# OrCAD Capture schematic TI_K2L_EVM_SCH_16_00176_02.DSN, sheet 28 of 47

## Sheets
28 PAGE15 : K2L_SOC-FPGA-AMC-1: size C; title: FPGA, SYSREF Buffering, LEDs
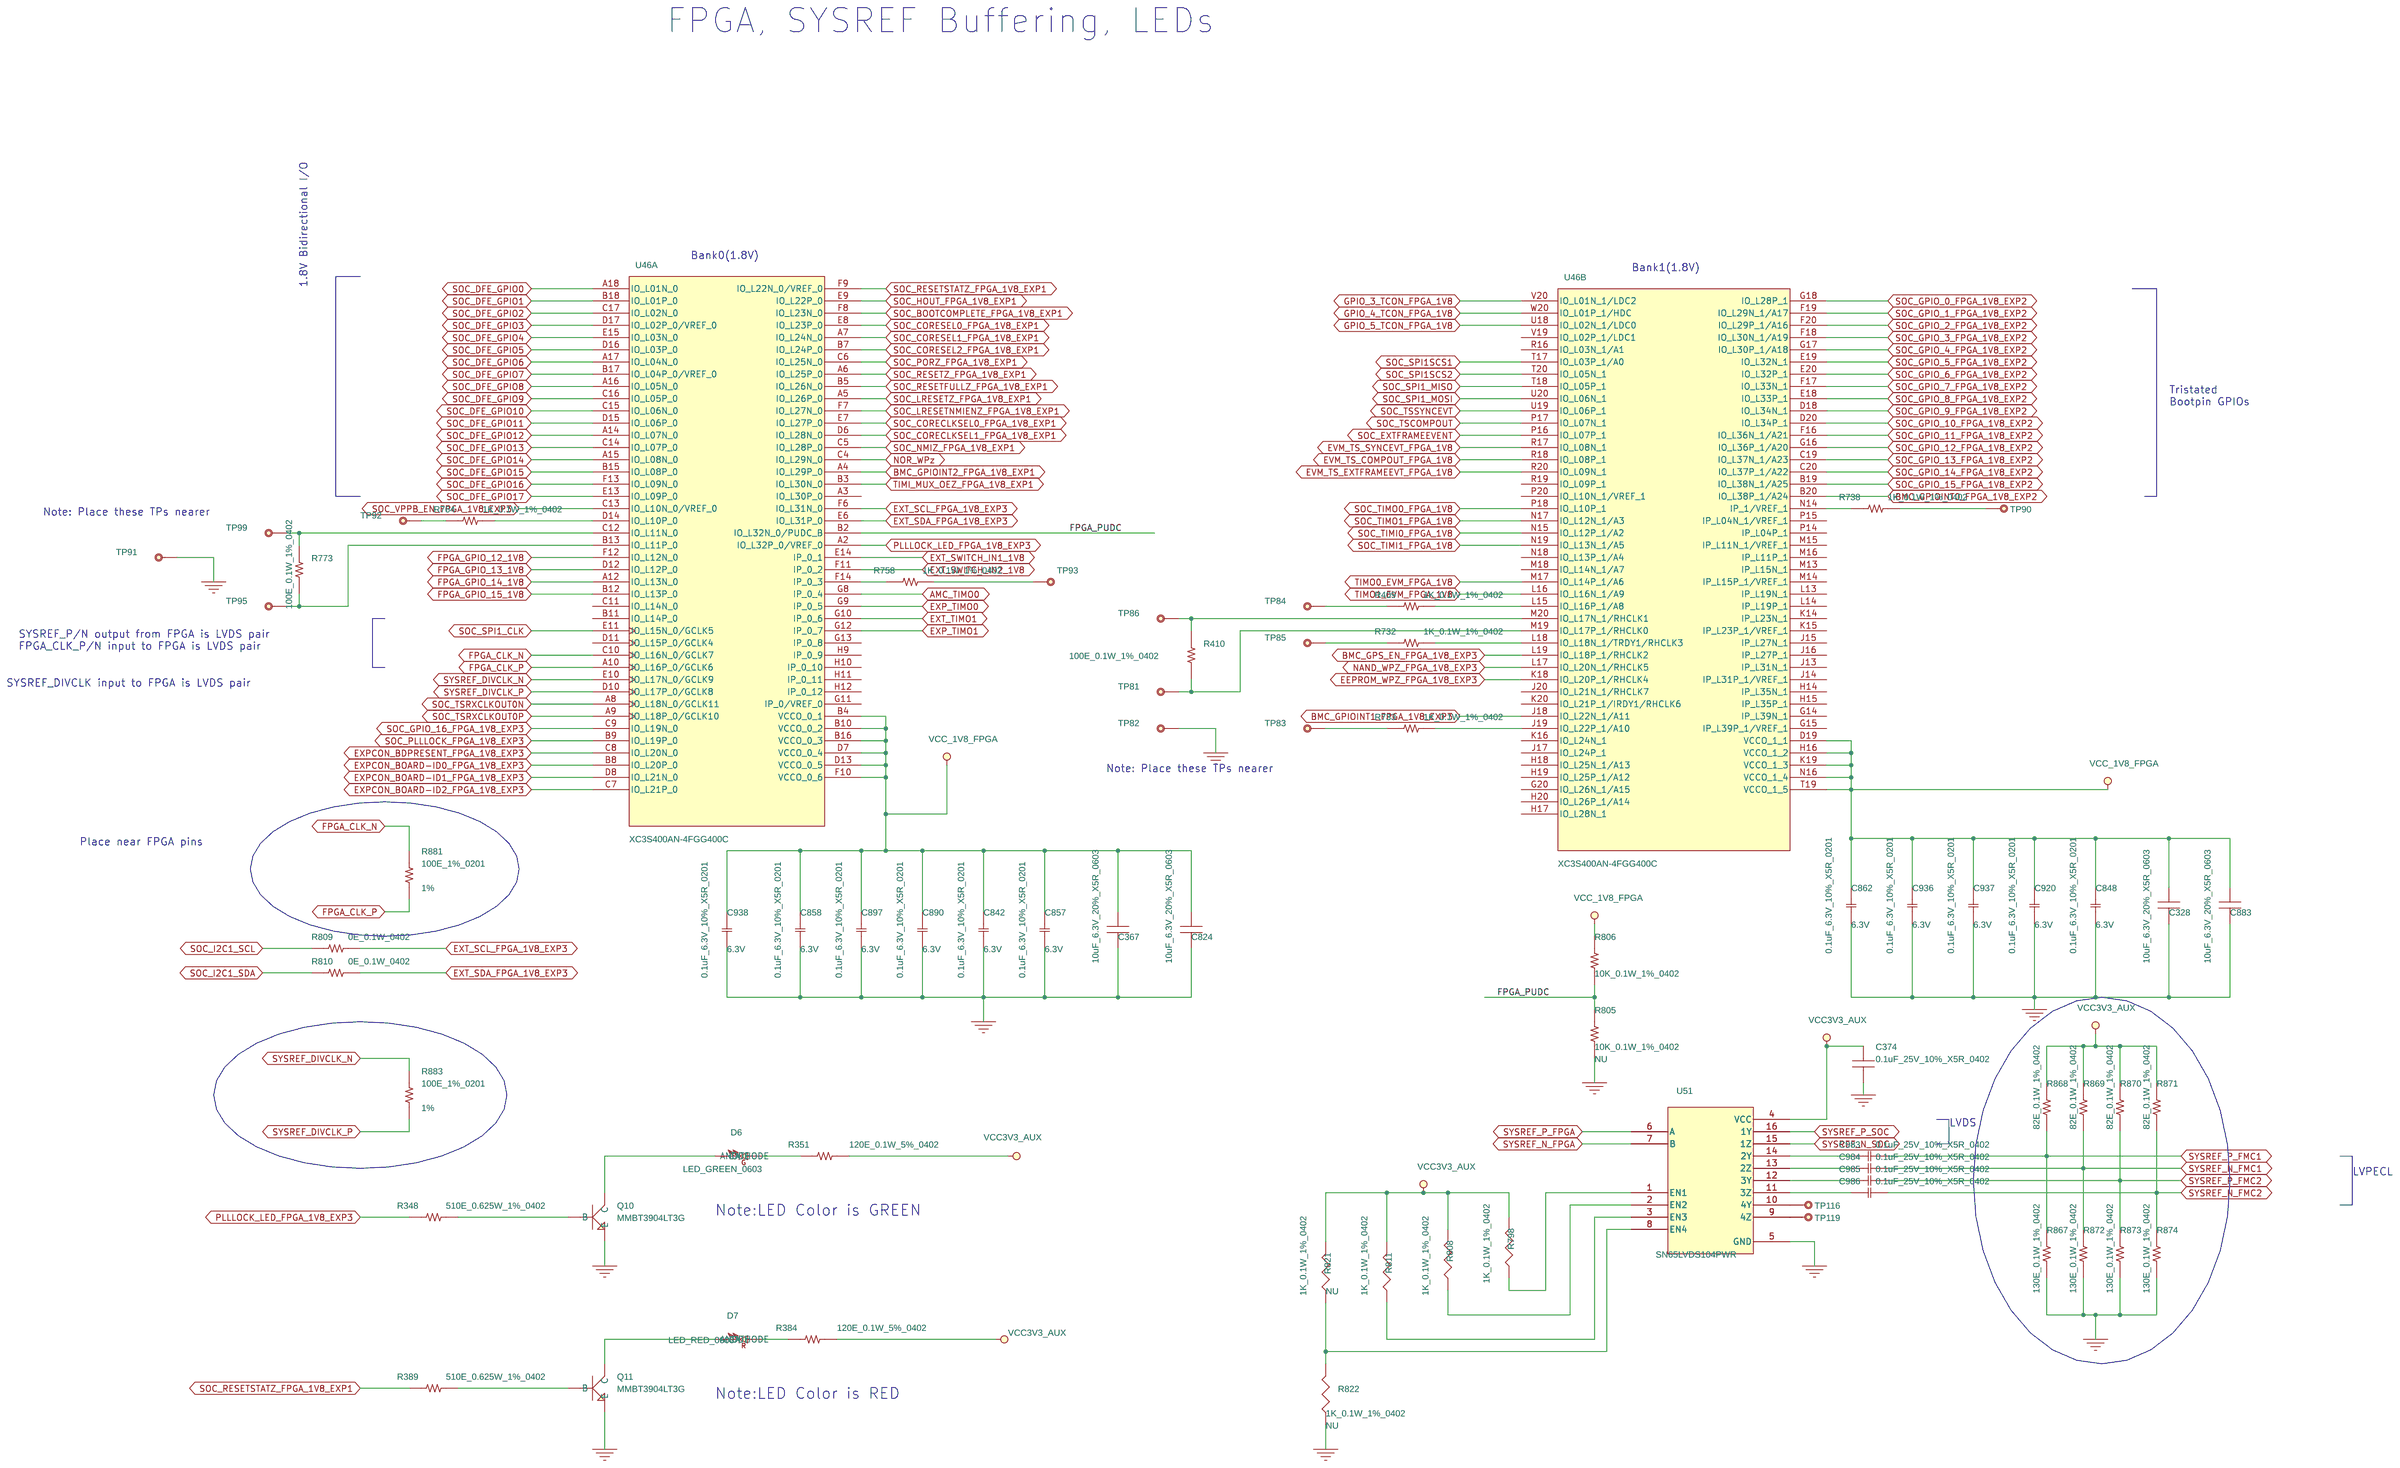
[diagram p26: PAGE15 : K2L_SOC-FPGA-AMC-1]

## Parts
sheet PAGE15 : K2L_SOC-FPGA-AMC-1
C328  10uF_6.3V_20%_X5R_0603  [C0603]
C367  10uF_6.3V_20%_X5R_0603  [C0603]
C374  0.1uF_25V_10%_X5R_0402  [C0402]
C824  10uF_6.3V_20%_X5R_0603  [C0603]
C842  0.1uF_6.3V_10%_X5R_0201  [CC0201_IPC7351_EINF]
C848  0.1uF_6.3V_10%_X5R_0201  [CC0201_IPC7351_EINF]
C857  0.1uF_6.3V_10%_X5R_0201  [CC0201_IPC7351_EINF]
C858  0.1uF_6.3V_10%_X5R_0201  [CC0201_IPC7351_EINF]
C862  0.1uF_6.3V_10%_X5R_0201  [CC0201_IPC7351_EINF]
C883  10uF_6.3V_20%_X5R_0603  [C0603]
C890  0.1uF_6.3V_10%_X5R_0201  [CC0201_IPC7351_EINF]
C897  0.1uF_6.3V_10%_X5R_0201  [CC0201_IPC7351_EINF]
C920  0.1uF_6.3V_10%_X5R_0201  [CC0201_IPC7351_EINF]
C936  0.1uF_6.3V_10%_X5R_0201  [CC0201_IPC7351_EINF]
C937  0.1uF_6.3V_10%_X5R_0201  [CC0201_IPC7351_EINF]
C938  0.1uF_6.3V_10%_X5R_0201  [CC0201_IPC7351_EINF]
C983  0.1uF_25V_10%_X5R_0402  [C0402]
C984  0.1uF_25V_10%_X5R_0402  [C0402]
C985  0.1uF_25V_10%_X5R_0402  [C0402]
C986  0.1uF_25V_10%_X5R_0402  [C0402]
D6  LED_GREEN_0603  [LED_0603]
D7  LED_RED_0603  [LED_0603]
Q10  MMBT3904LT3G  [SOT-23]
Q11  MMBT3904LT3G  [SOT-23]
R348  510E_0.625W_1%_0402  [R0402]
R351  120E_0.1W_5%_0402  [R0402]
R384  120E_0.1W_5%_0402  [R0402]
R389  510E_0.625W_1%_0402  [R0402]
R409  1K_0.1W_1%_0402  [R0402]
R410  100E_0.1W_1%_0402  [R0402]
R732  1K_0.1W_1%_0402  [R0402]
R733  1K_0.1W_1%_0402  [R0402]
R738  1K_0.1W_1%_0402  [R0402]
R758  1K_0.1W_1%_0402  [R0402]
R764  1K_0.1W_1%_0402  [R0402]
R773  100E_0.1W_1%_0402  [R0402]
R798  1K_0.1W_1%_0402  [R0402]
R805  10K_0.1W_1%_0402  [R0402]
R806  10K_0.1W_1%_0402  [R0402]
R808  1K_0.1W_1%_0402  [R0402]
R809  0E_0.1W_0402  [R0402]
R810  0E_0.1W_0402  [R0402]
R811  1K_0.1W_1%_0402  [R0402]
R821  1K_0.1W_1%_0402  [R0402]
R822  1K_0.1W_1%_0402  [R0402]
R867  130E_0.1W_1%_0402  [R0402]
R868  82E_0.1W_1%_0402  [R0402]
R869  82E_0.1W_1%_0402  [R0402]
R870  82E_0.1W_1%_0402  [R0402]
R871  82E_0.1W_1%_0402  [R0402]
R872  130E_0.1W_1%_0402  [R0402]
R873  130E_0.1W_1%_0402  [R0402]
R874  130E_0.1W_1%_0402  [R0402]
R881  100E_1%_0201  [RC0201_IPC7351_EINF]
R883  100E_1%_0201  [RC0201_IPC7351_EINF]
TP81  TP  [TP-S40]
TP82  TP  [TP-S40]
TP83  TP  [TP-S40]
TP84  TP  [TP-S40]
TP85  TP  [TP-S40]
TP86  TP  [TP-S40]
TP90  TP  [TP-S40]
TP91  TP  [TP-S40]
TP92  TP  [TP-S40]
TP93  TP  [TP-S40]
TP95  TP  [TP-S40]
TP99  TP  [TP-S40]
TP116  TP  [TP-S40]
TP119  TP  [TP-S40]
U51  SN65LVDS104PWR  [TSSOP65P640_16]
sheet PAGE17 : K2L_SOC-FPGA-AMC-3
U46  XC3S400AN-4FGG400C  [BGA400C100P20X20_2100X2100X243]  (sections A,B,C,D,E,F)

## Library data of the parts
C328 C367 C824 C883 = CAP: CAP CER 10UF 6.3V 20% X5R 0603; Distributor_name: DIGIKEY; Distributor_part_number: 587-3383-1-ND; EIC Part#: 03_00605_01; Manufacture: Taiyo Yuden; Manufacture Part Number: JMK107ABJ106MAHT; Manufacture(English): Taiyo Yuden; Manufacture_Part_Number: JMK107ABJ106MAHT; Manufacturer: Taiyo Yuden; Manufacturer_Part_No: JMK107ABJ106MAHT; Mfg: Taiyo Yuden; Mfg Part#: JMK107ABJ106MAHT; Mfr_name: Taiyo Yuden; Mfr_part_number: JMK107ABJ106MAHT; Price @ 1: 0.44000; Price @ 10K: 0.06105; Price @ 1K: 0.12650; Vendor: DIGIKEY; Vendor_Part_No: 587-3383-1-ND; eI Part#: 03_00605_01
C374 = CAP: CAP CER 0.1UF 25V 10% X5R 0402; Distributor_name: DIGIKEY; Distributor_part_number: 445-4964-1-ND; EIC Part#: 03_00470_02; Manufacture: TDK Corporation; Manufacture Part Number: C1005X5R1E104K050BC; Manufacture(English): TDK Corporation; Manufacture_Part_Number: GRM155R61E104KA87D; Manufacturer: TDK Corporation; Manufacturer_Part_No: C1005X5R1E104K050BC; Mfg: Murata Electronics North America; Mfg Part#: 03_00470_02; Mfr_name: TDK Corporation; Mfr_part_number: C1005X5R1E104K050BC; Price @ 1: 0.10000; Price @ 1K: 0.00960; Vendor: DIGIKEY; Vendor Part#: 445-4964-1-ND; Vendor_Part_No: 445-4964-1-ND; eI Part#: 03_00470_02
C842 C848 C857 C858 C862 C890 C897 C920 C936-C938 = 11_C_12: CAP CER 0.1UF 6.3V 10% X5R 0201; Alt Mfg: Taiyo Yuden; Alt Mfg Part#: TMK105BJ104KV-F; Characteristic: <Characteristic>; Distributor_name: DIGIKEY; Distributor_part_number: 445-1796-1-ND; EIC Part#: 03_00583_01; Manufacture: TDK Corporation; Manufacture Part Number: C0603X5R0J104K030BC; Manufacture(English): TDK Corporation; Manufacture_Part_Number: C0603X5R0J104K030BC; Manufacturer: TDK Corporation; Manufacturer_Part_No: C0603X5R0J104K030BC; Mfg: TDK Corporation; Mfg Part#: 03_00583_01; Mfr_name: TDK Corporation; Mfr_part_number: C0603X5R0J104K030BC; Oper. Temp. Range: -55°C ~ 85°C; Package: 0201; Price @ 1: 0.10000; Price @ 10K: 0.00675; Price @ 1K: 0.00810; ProcessType: SMT; RoHS: Yes; Tolerance: 10%; Vendor: DIGIKEY; Vendor Part#: 445-1796-2-ND; Vendor_Part_No: 445-1796-1-ND; Voltage: 6.3V; eI Part#: 03_00583_01
C983-C986 = 11_C_12: CAP CER 0.1UF 25V 10% X5R 0402; Alt Mfg: Taiyo Yuden; Distributor_name: DIGIKEY; Distributor_part_number: 445-4964-1-ND; EIC Part#: 03_00470_02; Manufacture: TDK Corporation; Manufacture Part Number: C1005X5R1E104K050BC; Manufacture(English): TDK Corporation; Manufacture_Part_Number: GRM155R61E104KA87D; Manufacturer: TDK Corporation; Manufacturer_Part_No: C1005X5R1E104K050BC; Mfg: Murata Electronics North America; Mfg Part#: 03_00470_02; Mfr_name: TDK Corporation; Mfr_part_number: C1005X5R1E104K050BC; Oper. Temp. Range: -55°C ~ 85°C; Package: 0402; Price @ 1: 0.10000; Price @ 1K: 0.00960; ProcessType: SMT; RoHS: Yes; Tolerance: 10%; Vendor: DIGIKEY; Vendor Part#: 445-4964-1-ND; Vendor_Part_No: 445-4964-1-ND; eI Part#: 03_00470_02
D6 = 130_LED_LED-0603_G_0: LED Green SMD 0603 KP-1608MGC; Distributor_name: Avnet Express; Distributor_part_number: KINKP1608MGC; EIC Part#: 06_00463_01; Manufacture: Kingbright Corporation; Manufacture Part Number: KP-1608MGC; Manufacture(English): Kingbright Corporation; Manufacture_Part_Number: KP-1608MGC; Manufacturer: Kingbright Corporation; Manufacturer_Part_No: KP-1608MGC; Mfg Part#: 06_00463_01; Mfr_name: Kingbright Corporation; Mfr_part_number: KP-1608MGC; Price @ 1: 0.66000; Price @ 10K: 0.31000; Price @ 1K: 0.31000; Vendor: Avnet Express; Vendor_Part_No: KINKP1608MGC; eI Part#: 06_00463_01
D7 = 130_LED_LED-0603_R_1: LED Red SMD 0603 KPT-1608EC; Distributor_name: ELEMENT14; Distributor_part_number: 2099221; EIC Part#: TBD; Manufacture: Kingbright Corporation; Manufacture Part Number: KPT-1608EC; Manufacture(English): Kingbright Corporation; Manufacture_Part_Number: KPT-1608EC; Manufacturer: Kingbright Corporation; Manufacturer_Part_No: KPT-1608EC; Mfg Part#: TBD; Mfr_name: Kingbright Corporation; Mfr_part_number: KPT-1608EC; Price @ 1: 0.11400; Price @ 10K: 0.07000; Price @ 1K: 0.07000; Vendor: ELEMENT14; Vendor_Part_No: 2099221; eI Part#: TBD
Q10 Q11 = 131_SOT-23A_BEC_0: TRANS NPN 2N3904 0.2A SMD TO-236AB; Distributor_name: DIGIKEY; Distributor_part_number: MMBT3904LT3GOSCT-ND; EIC Part#: 07_00016_04; Manufacture: ON Semiconductor; Manufacture(English): ON Semiconductor; Manufacturer: ON Semiconductor; Mfg Part#: 07_00016_04; Mfr_name: ON Semiconductor; Price @ 1: 0.11000; Price @ 10K: 0.01420; Price @ 1K: 0.02194; Vendor: DIGIKEY; Vendor_Part_No: MMBT3904LT3GOSCT-ND; eI Part#: 07_00016_04
R348 R389 = 10_R_0: RES 510 OHM 1/16W 1% 0402 SMD; Distributor_name: DIGIKEY; Distributor_part_number: 541-510LCT-ND; EIC Part#: 02_00958_01; Manufacture: Vishay Dale; Manufacture Part Number: CRCW0402510RFKED; Manufacture(English): Vishay Dale; Manufacture_Part_Number: CRCW0402510RFKED; Manufacturer: Vishay Dale; Manufacturer_Part_No: CRCW0402510RFKED; Mfg: Vishay Dale; Mfg Part#: CRCW0402510RFKED; Mfr_name: Vishay Dale; Mfr_part_number: CRCW0402510RFKED; Price @ 1: 0.10000; Price @ 10K: 0.00347; Price @ 1K: 0.00672; Vendor: DigiKey; Vendor_Part_No: 541-510LCT-ND; eI Part#: 02_00958_01
R351 = 10_R_0: RES 120 OHM 1/10W 5% 0402 SMD; Distributor_name: DIGIKEY; Distributor_part_number: P120JCT-ND; EIC Part#: TBD; Manufacture: Panasonic - ECG; Manufacture Part Number: ERJ-2GEJ121X; Manufacture(English): Panasonic - ECG; Manufacture_Part_Number: ERJ-2GEJ121X; Manufacturer: Panasonic - ECG; Manufacturer_Part_No: ERJ-2GEJ121X; Mfg Part#: TBD; Mfr_name: Panasonic - ECG; Mfr_part_number: ERJ-2GEJ121X; Price @ 1: 0.10000; Price @ 10K: 0.00248; Price @ 1K: 0.00480; Vendor: DIGIKEY; Vendor_Part_No: P120JCT-ND; eI Part#: 02_00199_01
R384 = 10_R_0: RES 120 OHM 1/10W 5% 0402 SMD; Distributor_name: DIGIKEY; Distributor_part_number: P120JCT-ND; EIC Part#: TBD; Manufacture: Panasonic - ECG; Manufacture Part Number: ERJ-2GEJ121X; Manufacture(English): Panasonic - ECG; Manufacture_Part_Number: ERJ-2GEJ121X; Manufacturer: Panasonic - ECG; Manufacturer_Part_No: ERJ-2GEJ121X; Mfg Part#: TBD; Mfr_name: Panasonic - ECG; Mfr_part_number: ERJ-2GEJ121X; Price @ 1: 0.10000; Price @ 10K: 0.00248; Price @ 1K: 0.00480; Vendor: DIGIKEY; Vendor_Part_No: P120JCT-ND; eI Part#: 02_00348_01
R409 R732 R733 R738 R758 R764 = 10_R_0: RES 1.00K OHM 1/10W 1% 0402 SMD; Distributor_name: DIGIKEY; Distributor_part_number: P1.00KLCT-ND; EIC Part#: 02_00045_01; Manufacture: Panasonic - ECG; Manufacture Part Number: ERJ-2RKF1001X; Manufacture(English): Panasonic - ECG; Manufacture_Part_Number: ERJ-2RKF1001X; Manufacturer: Panasonic - ECG; Manufacturer_Part_No: ERJ-2RKF1001X; Mfg Part#: 02_00045_01; Mfr_name: Panasonic - ECG; Mfr_part_number: ERJ-2RKF1001X; Price @ 1: 0.10000; Price @ 10K: 0.00347; Price @ 1K: 0.00672; Vendor: DIGIKEY; Vendor_Part_No: P1.00KLCT-ND; eI Part#: 02_00045_01
R410 = 10_R_0: RES 100 OHM 1/10W 1% 0402 SMD; Distributor_name: DIGIKEY; Distributor_part_number: P100LCT-ND; EIC Part#: 02_00043_02; Manufacture: Panasonic - ECG; Manufacture Part Number: ERJ-2RKF1000X; Manufacture(English): Panasonic - ECG; Manufacture_Part_Number: ERJ-2RKF1000X; Manufacturer: Panasonic - ECG; Manufacturer_Part_No: ERJ-2RKF1000X; Mfg Part#: 02_00043_02; Mfr_name: Panasonic - ECG; Mfr_part_number: ERJ-2RKF1000X; Price @ 1: 0.10000; Price @ 10K: 0.00347; Price @ 1K: 0.00672; Vendor: DIGIKEY; Vendor_Part_No: P100LCT-ND; eI Part#: 02_00025_01
R773 = 10_R_0: RES 100 OHM 1/10W 1% 0402 SMD; Distributor_name: DIGIKEY; Distributor_part_number: P100LCT-ND; EIC Part#: 02_00043_02; Manufacture: Panasonic - ECG; Manufacture Part Number: ERJ-2RKF1000X; Manufacture(English): Panasonic - ECG; Manufacture_Part_Number: ERJ-2RKF1000X; Manufacturer: Panasonic - ECG; Manufacturer_Part_No: ERJ-2RKF1000X; Mfg Part#: 02_00043_02; Mfr_name: Panasonic - ECG; Mfr_part_number: ERJ-2RKF1000X; Price @ 1: 0.10000; Price @ 10K: 0.00347; Price @ 1K: 0.00672; Vendor: DIGIKEY; Vendor_Part_No: P100LCT-ND; eI Part#: 02_00024_01
R798 R808 R811 = RESISTOR: RES 1.00K OHM 1/10W 1% 0402 SMD; Distributor_name: DIGIKEY; Distributor_part_number: P1.00KLCT-ND; EI Part#: 02_00045_01; EIC Part#: 02_00045_01; Manufacture: Panasonic - ECG; Manufacture Part Number: ERJ-2RKF1001X; Manufacture(English): Panasonic - ECG; Manufacture_Part_Number: ERJ-2RKF1001X; Manufacturer: Panasonic - ECG; Manufacturer_Part_No: ERJ-2RKF1001X; Mfg Part#: 02_00045_01; Mfr_name: Panasonic - ECG; Mfr_part_number: ERJ-2RKF1001X; Price @ 1: 0.10000; Price @ 10K: 0.00347; Price @ 1K: 0.00672; Vendor: DIGIKEY; Vendor_Part_No: P1.00KLCT-ND
R805 = 10_R_0: RES 10K OHM 1/10W 1% 0402 SMD; Distributor_name: DIGIKEY; Distributor_part_number: P10.0KLCT-ND; EIC Part#: 02_00027_01; Manufacture: Panasonic - ECG; Manufacture Part Number: ERJ-2RKF1002X; Manufacture(English): Panasonic - ECG; Manufacture_Part_Number: ERJ-2RKF1002X; Manufacturer: Panasonic - ECG; Manufacturer_Part_No: ERJ-2RKF1002X; Mfg Part#: 02_00027_01; Mfr_name: Panasonic - ECG; Mfr_part_number: ERJ-2RKF1002X; Mounting: NU; Mounting Status: NU; Mounting_Status: NU; Package: 0402; Price @ 1: 0.10000; Price @ 10K: 0.00347; Price @ 1K: 0.00672; Vendor: DIGIKEY; Vendor_Part_No: P10.0KLCT-ND; eI Part#: 02_00027_01
R806 = 10_R_0: RES 10K OHM 1/10W 1% 0402 SMD; Distributor_name: DIGIKEY; Distributor_part_number: P10.0KLCT-ND; EIC Part#: 02_00027_01; Manufacture: Panasonic - ECG; Manufacture Part Number: ERJ-2RKF1002X; Manufacture(English): Panasonic - ECG; Manufacture_Part_Number: ERJ-2RKF1002X; Manufacturer: Panasonic - ECG; Manufacturer_Part_No: ERJ-2RKF1002X; Mfg Part#: 02_00027_01; Mfr_name: Panasonic - ECG; Mfr_part_number: ERJ-2RKF1002X; Package: 0402; Price @ 1: 0.10000; Price @ 10K: 0.00347; Price @ 1K: 0.00672; Vendor: DIGIKEY; Vendor_Part_No: P10.0KLCT-ND; eI Part#: 02_00027_01
R809 R810 = 10_R_0: RES 0.0 OHM 1/10W JUMP 0402 SMD; Distributor_name: DIGIKEY; Distributor_part_number: P0.0JCT-ND; EIC Part#: 02_00019_01; Manufacture: Panasonic - ECG; Manufacture Part Number: ERJ-2GE0R00X; Manufacture(English): Panasonic - ECG; Manufacture_Part_Number: ERJ-2GE0R00X; Manufacturer: Panasonic - ECG; Manufacturer_Part_No: ERJ-2GE0R00X; Mfg: PANASONIC ELECTRONIC COMPONENTS (VA); Mfg Part#: 02_00019_01; Mfr_name: Panasonic - ECG; Mfr_part_number: ERJ-2GE0R00X; Price @ 1: 0.05000; Price @ 10K: 0.00248; Price @ 1K: 0.00480; Vendor: DIGIKEY; Vendor_Part_No: P0.0JCT-ND; eI Part#: 02_00019_01
R821 R822 = RESISTOR: RES 1.00K OHM 1/10W 1% 0402 SMD; Distributor_name: DIGIKEY; Distributor_part_number: P1.00KLCT-ND; EI Part#: 02_00045_01; EIC Part#: 02_00045_01; Manufacture: Panasonic - ECG; Manufacture Part Number: ERJ-2RKF1001X; Manufacture(English): Panasonic - ECG; Manufacture_Part_Number: ERJ-2RKF1001X; Manufacturer: Panasonic - ECG; Manufacturer_Part_No: ERJ-2RKF1001X; Mfg Part#: 02_00045_01; Mfr_name: Panasonic - ECG; Mfr_part_number: ERJ-2RKF1001X; Mounting Status: NU; Mounting_Status: NU; Price @ 1: 0.10000; Price @ 10K: 0.00347; Price @ 1K: 0.00672; Vendor: DIGIKEY; Vendor_Part_No: P1.00KLCT-ND
R867 R872-R874 = 10_R_0: RES 130 OHM 1/10W 1% 0402 SMD; Distributor_name: DIGIKEY; Distributor_part_number: P130LCT-ND; EIC Part#: TBD; Manufacture: Panasonic - ECG; Manufacture Part Number: ERJ-2RKF1300X; Manufacture(English): Panasonic - ECG; Manufacture_Part_Number: ERJ-2RKF1300X; Manufacturer: Panasonic - ECG; Manufacturer_Part_No: ERJ-2RKF1300X; Mfg: Panasonic - ECG; Mfg Part#: Panasonic - ECG; Mfr_name: Panasonic - ECG; Mfr_part_number: ERJ-2RKF1300X; Package: 0402; Price @ 1: 0.10000; Price @ 10K: 0.00347; Price @ 1K: 0.00672; Vendor: DIGIKEY; Vendor_Part_No: P130LCT-ND; eI Part#: TBD
R868-R871 = 10_R_0: RES 82 OHM 1/10W 1% 0402 SMD; Distributor_name: DIGIKEY; Distributor_part_number: P10.0KLCT-ND; EIC Part#: TBD; Manufacture: Panasonic - ECG; Manufacture Part Number: ERJ-2RKF82R0X; Manufacture(English): Panasonic - ECG; Manufacture_Part_Number: ERJ-2RKF82R0X; Manufacturer: Panasonic - ECG; Manufacturer_Part_No: ERJ-2RKF82R0X; Mfg: Panasonic - ECG; Mfg Part#: Panasonic - ECG; Mfr_name: Panasonic - ECG; Mfr_part_number: ERJ-2RKF82R0X; Package: 0402; Price @ 1: 0.10000; Price @ 10K: 0.00347; Price @ 1K: 0.00672; Vendor: DIGIKEY; Vendor_Part_No: P82.0LCT-ND; eI Part#: TBD
R881 R883 = 10_R_0: RES 100 OHM 1/20W 1% 0201 SMD; Characteristic: 1%; Distributor_name: DIGIKEY; EIC Part#: 02_00043_02; Manufacture: Panasonic - ECG; Manufacture Part Number: ERJ-1GEF1000C; Manufacture(English): Panasonic - ECG; Manufacture_Part_Number: ERJ-1GEF1000C; Manufacturer: Panasonic - ECG; Manufacturer_Part_No: ERJ-1GEF1000C; Mfg: Panasonic - ECG; Mfg Part#: ERJ-1GEF1000C; Mfr_name: Panasonic - ECG; Mfr_part_number: ERJ-1GEF1000C; Package: 0201; ProcessType: SMT; RoHS: Yes; Tolerance: 1%; Vendor: Digikey; Vendor Part#: P100ABCT-ND; Vendor_Part_No: P100ABCT-ND; eI Part#: 02_00043_02
TP81-TP83 TP85 TP90 TP91 = 00_TP28_0: TEST PAD TP; Distributor_name: NA; Distributor_part_number: NA; EIC Part#: NA; Manufacture: NA; Manufacture Part Number: NA; Manufacture(English): NA; Manufacture_Part_Number: NA; Manufacturer: NA; Manufacturer_Part_No: NA; Mfg: NA; Mfg Part#: NA; Mfr_name: NA; Mfr_part_number: NA; Price @ 1: NA; Price @ 10K: NA; Price @ 1K: NA; Vendor: NA; Vendor_Part_No: NA; eI Part#: TBD
TP84 = 00_TP28_0: TEST PAD TP; Distributor_name: NA; Distributor_part_number: NA; EIC Part#: NA; Manufacture: NA; Manufacture Part Number: NA; Manufacture(English): NA; Manufacture_Part_Number: NA; Manufacturer: NA; Manufacturer_Part_No: NA; Mfg: NA; Mfg Part#: NA; Mfr_name: NA; Mfr_part_number: NA; Price @ 1: NA; Price @ 10K: NA; Price @ 1K: NA; Vendor: NA; Vendor_Part_No: NA; eI Part#: 01_00854_01
TP86 = 00_TP28_0: TEST PAD TP; Distributor_name: NA; Distributor_part_number: NA; EIC Part#: NA; Manufacture: NA; Manufacture Part Number: NA; Manufacture(English): NA; Manufacture_Part_Number: NA; Manufacturer: NA; Manufacturer_Part_No: NA; Mfg: NA; Mfg Part#: NA; Mfr_name: NA; Mfr_part_number: NA; Price @ 1: NA; Price @ 10K: NA; Price @ 1K: NA; Vendor: NA; Vendor_Part_No: NA; eI Part#: 01_01117_01
TP92 TP116 TP119 = 00_TP28_0: TEST PAD TP; Distributor_name: NA; Distributor_part_number: NA; EIC Part#: NA; Manufacture: NA; Manufacture Part Number: NA; Manufacture(English): NA; Manufacture_Part_Number: NA; Manufacturer: NA; Manufacturer_Part_No: NA; Mfg: NA; Mfg Part#: NA; Mfr_name: NA; Mfr_part_number: NA; Price @ 1: NA; Price @ 10K: NA; Price @ 1K: NA; Vendor: NA; Vendor_Part_No: NA; eI Part#: NA
TP93 = 00_TP28_0: TEST PAD TP; Distributor_name: NA; Distributor_part_number: NA; EIC Part#: NA; Manufacture: NA; Manufacture Part Number: NA; Manufacture(English): NA; Manufacture_Part_Number: NA; Manufacturer: NA; Manufacturer_Part_No: NA; Mfg: NA; Mfg Part#: NA; Mfr_name: NA; Mfr_part_number: NA; Price @ 1: NA; Price @ 10K: NA; Price @ 1K: NA; Vendor: NA; Vendor_Part_No: NA; eI Part#: 01_00390_01
TP95 TP99 = 00_TP28_0: TEST PAD TP; Distributor_name: NA; Distributor_part_number: NA; EIC Part#: NA; Manufacture: NA; Manufacture Part Number: NA; Manufacture(English): NA; Manufacture_Part_Number: NA; Manufacturer: NA; Manufacturer_Part_No: NA; Mfg: NA; Mfg Part#: NA; Mfr_name: NA; Mfr_part_number: NA; Price @ 1: NA; Price @ 10K: NA; Price @ 1K: NA; Vendor: NA; Vendor_Part_No: NA; eI Part#: 01_01119_01
U51 = IC_BUF_SN65LVDS104PWR: IC 1:4 LVDS CLOCK BUFFER 16TSSOP; Distributor_name: DIGIKEY; Distributor_part_number: 296-26359-1-ND; EIC Part#: TBD; Manufacture: TI; Manufacture(English): TI; Manufacturer: TI; Mfg: TI; Mfg Part#: TBD; Mfr_name: TI; Price @ 1: 4.46000; Price @ 10K: 2.06150; Price @ 1K: 2.23200; Vendor: DIGIKEY; Vendor_Part_No: 296-26359-1-ND; eI Part#: 08_00172_01
U46 = XC3S400AN-4FGG400C: IC SPARTAN-3AN FPGA 400K 400FBGA; Color: Default; Distributor_name: DIGIKEY; Distributor_part_number: 122-1554-ND; EIC Part#: 01_01149_01; Location X-Coordinate: 0; Location Y-Coordinate: 0; Manufacture: Xilinx Inc; Manufacture(English): Xilinx Inc; Manufacturer: Xilinx Inc; Mfg: Xilinx Inc; Mfg Part#: 01_01149_01; Mfr_name: Xilinx Inc; Price @ 1: 27.86000; Primitive: DEFAULT; SPLIT_INST: TRUE; SWAP_INFO: (S1+S2+S3+S4+S5+S6); Vendor: DIGIKEY; Vendor_Part_No: 122-1554-ND; eI Part#: 01_01138_01

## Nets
GND: C328.2 C367.2 C374.2 C824.2 C842.2 C848.2 C857.2 C858.2 C862.2 C883.2 C890.2 C897.2 C920.2 C936.2 C937.2 C938.2 Q10.2(E) Q11.2(E) R805.1 R822.2 R867.1 R872.1 R873.1 R874.1 TP82.1 TP91.1 U51.5(GND) ; also on sheet 1 2 3 4 5 6 8 10 11 12 13 14 15 16 17 18 19 20 21 22 24 25 26 27 29 33 34 35 36 37 40 41 42 43 45 46 47
VCC3V3_AUX: C374.1 R351.2 R384.2 R798.1 R808.1 R811.1 R821.1 R868.2 R869.2 R870.2 R871.2 U51.4(VCC) ; also on sheet 2 4 6 8 11 12 13 16 18 19 22 25 26 27 29 33 35 37 40 45 47
VCC_1V8_FPGA: C328.1 C367.1 C824.1 C842.1 C848.1 C857.1 C858.1 C862.1 C883.1 C890.1 C897.1 C920.1 C936.1 C937.1 C938.1 R806.2 U46.B4(VCCO_0_1) U46.B10(VCCO_0_2) U46.B16(VCCO_0_3) U46.D7(VCCO_0_4) U46.D13(VCCO_0_5) U46.D19(VCCO_1_1) U46.F10(VCCO_0_6) U46.H16(VCCO_1_2) U46.K19(VCCO_1_3) U46.N16(VCCO_1_4) U46.T19(VCCO_1_5) ; also on sheet 27 29 35
AMC_TIMO0: U46.G8(IP_0_4) ; also on sheet 18
BMC_GPIOINT0_FPGA_1V8_EXP2: U46.B20(IO_L38P_1/A24) ; also on sheet 22
BMC_GPIOINT1_FPGA_1V8_EXP3: U46.J18(IO_L22N_1/A11) ; also on sheet 22
BMC_GPIOINT2_FPGA_1V8_EXP1: U46.A4(IO_L29P_0) ; also on sheet 22
BMC_GPS_EN_FPGA_1V8_EXP3: U46.L19(IO_L18P_1/RHCLK2) ; also on sheet 22
EEPROM_WPZ_FPGA_1V8_EXP3: U46.K18(IO_L20P_1/RHCLK4) ; also on sheet 41
EVM_TS_COMPOUT_FPGA_1V8: U46.R18(IO_L08P_1) ; also on sheet 26
EVM_TS_EXTFRAMEEVT_FPGA_1V8: U46.R20(IO_L09N_1) ; also on sheet 26
EVM_TS_SYNCEVT_FPGA_1V8: U46.R17(IO_L08N_1) ; also on sheet 26
EXP_TIMO0: U46.G9(IP_0_5) ; also on sheet 26
EXP_TIMO1: U46.G12(IP_0_7) ; also on sheet 26
EXPCON_BDPRESENT_FPGA_1V8_EXP3: U46.C8(IO_L20N_0) ; also on sheet 26
EXPCON_BOARD-ID0_FPGA_1V8_EXP3: U46.B8(IO_L20P_0) ; also on sheet 26
EXPCON_BOARD-ID1_FPGA_1V8_EXP3: U46.D8(IO_L21N_0) ; also on sheet 26
EXPCON_BOARD-ID2_FPGA_1V8_EXP3: U46.C7(IO_L21P_0) ; also on sheet 26
EXT_SCL_FPGA_1V8_EXP3: R809.2 U46.F6(IO_L31N_0)
EXT_SDA_FPGA_1V8_EXP3: R810.2 U46.E6(IO_L31P_0)
EXT_SWITCH_IN1_1V8: U46.E14(IP_0_1) ; also on sheet 27
EXT_SWITCH_IN2_1V8: U46.F11(IP_0_2) ; also on sheet 27
EXT_TIMO1: U46.G10(IP_0_6) ; also on sheet 26
FPGA_CLK_N: R881.2 U46.C10(IO_L16N_0/GCLK7) ; also on sheet 11
FPGA_CLK_P: R881.1 U46.A10(IO_L16P_0/GCLK6) ; also on sheet 11
FPGA_GPIO_12_1V8: U46.F12(IO_L12N_0) ; also on sheet 27
FPGA_GPIO_13_1V8: U46.D12(IO_L12P_0) ; also on sheet 27
FPGA_GPIO_14_1V8: U46.A12(IO_L13N_0) ; also on sheet 27
FPGA_GPIO_15_1V8: U46.B12(IO_L13P_0) ; also on sheet 27
FPGA_PUDC: R805.2 R806.1 U46.B2(IO_L32N_0/PUDC_B)
GPIO_3_TCON_FPGA_1V8: U46.V20(IO_L01N_1/LDC2) ; also on sheet 29
GPIO_4_TCON_FPGA_1V8: U46.W20(IO_L01P_1/HDC) ; also on sheet 29
GPIO_5_TCON_FPGA_1V8: U46.U18(IO_L02N_1/LDC0) ; also on sheet 29
NAND_WPZ_FPGA_1V8_EXP3: U46.L17(IO_L20N_1/RHCLK5) ; also on sheet 41
NOR_WPz: U46.C4(IO_L29N_0) ; also on sheet 27
PLLLOCK_LED_FPGA_1V8_EXP3: R348.1 U46.A2(IO_L32P_0/VREF_0)
SOC_BOOTCOMPLETE_FPGA_1V8_EXP1: U46.F8(IO_L23N_0) ; also on sheet 16
SOC_CORECLKSEL0_FPGA_1V8_EXP1: U46.E7(IO_L27P_0) ; also on sheet 16
SOC_CORECLKSEL1_FPGA_1V8_EXP1: U46.D6(IO_L28N_0) ; also on sheet 16
SOC_CORESEL0_FPGA_1V8_EXP1: U46.E8(IO_L23P_0) ; also on sheet 16
SOC_CORESEL1_FPGA_1V8_EXP1: U46.A7(IO_L24N_0) ; also on sheet 16
SOC_CORESEL2_FPGA_1V8_EXP1: U46.B7(IO_L24P_0) ; also on sheet 16
SOC_DFE_GPIO0: U46.A18(IO_L01N_0) ; also on sheet 16
SOC_DFE_GPIO1: U46.B18(IO_L01P_0) ; also on sheet 16
SOC_DFE_GPIO2: U46.C17(IO_L02N_0) ; also on sheet 16
SOC_DFE_GPIO3: U46.D17(IO_L02P_0/VREF_0) ; also on sheet 16
SOC_DFE_GPIO4: U46.E15(IO_L03N_0) ; also on sheet 16
SOC_DFE_GPIO5: U46.D16(IO_L03P_0) ; also on sheet 16
SOC_DFE_GPIO6: U46.A17(IO_L04N_0) ; also on sheet 16
SOC_DFE_GPIO7: U46.B17(IO_L04P_0/VREF_0) ; also on sheet 16
SOC_DFE_GPIO8: U46.A16(IO_L05N_0) ; also on sheet 16
SOC_DFE_GPIO9: U46.C16(IO_L05P_0) ; also on sheet 16
SOC_DFE_GPIO10: U46.C15(IO_L06N_0) ; also on sheet 16
SOC_DFE_GPIO11: U46.D15(IO_L06P_0) ; also on sheet 16
SOC_DFE_GPIO12: U46.A14(IO_L07N_0) ; also on sheet 16
SOC_DFE_GPIO13: U46.C14(IO_L07P_0) ; also on sheet 16
SOC_DFE_GPIO14: U46.A15(IO_L08N_0) ; also on sheet 16
SOC_DFE_GPIO15: U46.B15(IO_L08P_0) ; also on sheet 16
SOC_DFE_GPIO16: U46.F13(IO_L09N_0) ; also on sheet 16
SOC_DFE_GPIO17: U46.E13(IO_L09P_0) ; also on sheet 16
SOC_EXTFRAMEEVENT: U46.P16(IO_L07P_1) ; also on sheet 29
SOC_GPIO_0_FPGA_1V8_EXP2: U46.G18(IO_L28P_1) ; also on sheet 16 21
SOC_GPIO_1_FPGA_1V8_EXP2: U46.F19(IO_L29N_1/A17) ; also on sheet 16 21
SOC_GPIO_2_FPGA_1V8_EXP2: U46.F20(IO_L29P_1/A16) ; also on sheet 16 21
SOC_GPIO_3_FPGA_1V8_EXP2: U46.F18(IO_L30N_1/A19) ; also on sheet 16 21
SOC_GPIO_4_FPGA_1V8_EXP2: U46.G17(IO_L30P_1/A18) ; also on sheet 16 21
SOC_GPIO_5_FPGA_1V8_EXP2: U46.E19(IO_L32N_1) ; also on sheet 16 21
SOC_GPIO_6_FPGA_1V8_EXP2: U46.E20(IO_L32P_1) ; also on sheet 16 21
SOC_GPIO_7_FPGA_1V8_EXP2: U46.F17(IO_L33N_1) ; also on sheet 6 16 21
SOC_GPIO_8_FPGA_1V8_EXP2: U46.E18(IO_L33P_1) ; also on sheet 16 21 22
SOC_GPIO_9_FPGA_1V8_EXP2: U46.D18(IO_L34N_1) ; also on sheet 16 21
SOC_GPIO_10_FPGA_1V8_EXP2: U46.D20(IO_L34P_1) ; also on sheet 16 21
SOC_GPIO_11_FPGA_1V8_EXP2: U46.F16(IO_L36N_1/A21) ; also on sheet 16 21 22
SOC_GPIO_12_FPGA_1V8_EXP2: U46.G16(IO_L36P_1/A20) ; also on sheet 16 21
SOC_GPIO_13_FPGA_1V8_EXP2: U46.C19(IO_L37N_1/A23) ; also on sheet 16 21
SOC_GPIO_14_FPGA_1V8_EXP2: U46.C20(IO_L37P_1/A22) ; also on sheet 16 21
SOC_GPIO_15_FPGA_1V8_EXP2: U46.B19(IO_L38N_1/A25) ; also on sheet 16 21
SOC_GPIO_16_FPGA_1V8_EXP3: U46.C9(IO_L19N_0) ; also on sheet 16 21
SOC_HOUT_FPGA_1V8_EXP1: U46.E9(IO_L22P_0) ; also on sheet 16
SOC_I2C1_SCL: R809.1 ; also on sheet 19 29
SOC_I2C1_SDA: R810.1 ; also on sheet 19 29
SOC_LRESETNMIENZ_FPGA_1V8_EXP1: U46.F7(IO_L27N_0) ; also on sheet 16
SOC_LRESETZ_FPGA_1V8_EXP1: U46.A5(IO_L26P_0) ; also on sheet 16
SOC_NMIZ_FPGA_1V8_EXP1: U46.C5(IO_L28P_0) ; also on sheet 16
SOC_PLLLOCK_FPGA_1V8_EXP3: U46.B9(IO_L19P_0) ; also on sheet 16
SOC_PORZ_FPGA_1V8_EXP1: U46.C6(IO_L25N_0) ; also on sheet 16 29
SOC_RESETFULLZ_FPGA_1V8_EXP1: U46.B5(IO_L26N_0) ; also on sheet 16 29
SOC_RESETSTATZ_FPGA_1V8_EXP1: R389.1 U46.F9(IO_L22N_0/VREF_0) ; also on sheet 16
SOC_RESETZ_FPGA_1V8_EXP1: U46.A6(IO_L25P_0) ; also on sheet 16 29
SOC_SPI1_CLK: U46.E11(IO_L15N_0/GCLK5) ; also on sheet 11 29
SOC_SPI1_MISO: U46.T18(IO_L05P_1) ; also on sheet 29
SOC_SPI1_MOSI: U46.U20(IO_L06N_1) ; also on sheet 11 29
SOC_SPI1SCS1: U46.T17(IO_L03P_1/A0) ; also on sheet 29
SOC_SPI1SCS2: U46.T20(IO_L05N_1) ; also on sheet 29
SOC_TIMI0_FPGA_1V8: U46.N15(IO_L12P_1/A2) ; also on sheet 29
SOC_TIMI1_FPGA_1V8: U46.N19(IO_L13N_1/A5) ; also on sheet 29
SOC_TIMO0_FPGA_1V8: U46.P18(IO_L10P_1) ; also on sheet 29
SOC_TIMO1_FPGA_1V8: U46.N17(IO_L12N_1/A3) ; also on sheet 29
SOC_TSCOMPOUT: U46.P17(IO_L07N_1) ; also on sheet 29
SOC_TSRXCLKOUT0N: U46.A8(IO_L18N_0/GCLK11) ; also on sheet 26 29
SOC_TSRXCLKOUT0P: U46.A9(IO_L18P_0/GCLK10) ; also on sheet 26 29
SOC_TSSYNCEVT: U46.U19(IO_L06P_1) ; also on sheet 29
SOC_VPPB_EN_FPGA_1V8_EXP3: U46.C13(IO_L10N_0/VREF_0) ; also on sheet 25
SYSREF_DIVCLK_N: R883.2 U46.E10(IO_L17N_0/GCLK9) ; also on sheet 11
SYSREF_DIVCLK_P: R883.1 U46.D10(IO_L17P_0/GCLK8) ; also on sheet 11
SYSREF_N_FMC1: C984.2 R869.1 R872.2 ; also on sheet 43
SYSREF_N_FMC2: C986.2 R871.1 R874.2 ; also on sheet 46
SYSREF_N_FPGA: U51.7(B) ; also on sheet 27
SYSREF_N_SOC: U51.15(1Z) ; also on sheet 16
SYSREF_P_FMC1: C983.2 R867.2 R868.1 ; also on sheet 43
SYSREF_P_FMC2: C985.2 R870.1 R873.2 ; also on sheet 46
SYSREF_P_FPGA: U51.6(A) ; also on sheet 27
SYSREF_P_SOC: U51.16(1Y) ; also on sheet 16
TIMI_MUX_OEZ_FPGA_1V8_EXP1: U46.B3(IO_L30N_0) ; also on sheet 26
TIMO0_EVM_FPGA_1V8: U46.M17(IO_L14P_1/A6) ; also on sheet 18 26
TIMO1_EVM_FPGA_1V8: U46.L16(IO_L16N_1/A9) ; also on sheet 26
N17636831: Q10.1(B) R348.2
N17636849: D6.1(ANODE) R351.1
N17636853: D6.2(CATHODE) Q10.3(C)
N17638819: D7.1(ANODE) R384.1
N17638821: D7.2(CATHODE) Q11.3(C)
N17638854: Q11.1(B) R389.2
N17642805: R821.2 R822.1 U51.8(EN4)
N17642863: R798.2 U51.1(EN1)
N17642877: R808.2 U51.2(EN2)
N17642891: R811.2 U51.3(EN3)
N18908486: R764.1 U46.D14(IO_L10P_0)
N18908858: R758.2 U46.F14(IP_0_3)
N18910230: R764.2 TP92.1
N18910233: R773.2 TP99.1 U46.C12(IO_L11N_0)
N18910236: R773.1 TP95.1 U46.B13(IO_L11P_0)
N18910555: R409.1 U46.L15(IO_L16P_1/A8)
N18910557: R409.2 TP84.1
N18910607: R410.2 TP86.1 U46.M20(IO_L17N_1/RHCLK1)
N18910609: R410.1 TP81.1 U46.M19(IO_L17P_1/RHCLK0)
N18910711: R732.1 U46.L18(IO_L18N_1/TRDY1/RHCLK3)
N18910723: R732.2 TP85.1
N18910759: R738.2 U46.N14(IP_1/VREF_1)
N18915416: R733.1 U46.J19(IO_L22P_1/A10)
N18915419: R733.2 TP83.1
N19865350: R758.1 TP93.1
N19868212: R738.1 TP90.1
N23020233: C983.1 U51.14(2Y)
N23020236: C984.1 U51.13(2Z)
N23020239: C985.1 U51.12(3Y)
N23020242: C986.1 U51.11(3Z)
N23106365: TP119.1 U51.9(4Z)
N23106366: TP116.1 U51.10(4Y)

Not connected (* = marked no-connect by the designer): U46 A3(IO_L30P_0) B11(IO_L14P_0) C11(IO_L14N_0) D11(IO_L15P_0/GCLK4) G11(IP_0/VREF_0) G13(IP_0_8) G14(IP_L39N_1) G15(IP_L39P_1/VREF_1) G20(IO_L26N_1/A15) H9(IP_0_9) H10(IP_0_10) H11(IP_0_11) H12(IP_0_12) H14(IP_L35N_1) H15(IP_L35P_1) H17(IO_L28N_1) H18(IO_L25N_1/A13) H19(IO_L25P_1/A12) H20(IO_L26P_1/A14) J13(IP_L31N_1) J14(IP_L31P_1/VREF_1) J15(IP_L27N_1) J16(IP_L27P_1) J17(IO_L24P_1) J20(IO_L21N_1/RHCLK7) K14(IP_L23N_1) K15(IP_L23P_1/VREF_1) K16(IO_L24N_1) K20(IO_L21P_1/IRDY1/RHCLK6) L13(IP_L19N_1) L14(IP_L19P_1) M13(IP_L15N_1) M14(IP_L15P_1/VREF_1) M15(IP_L11N_1/VREF_1) M16(IP_L11P_1) M18(IO_L14N_1/A7) N18(IO_L13P_1/A4) P14(IP_L04P_1) P15(IP_L04N_1/VREF_1) P20(IO_L10N_1/VREF_1) R16(IO_L03N_1/A1) R19(IO_L09P_1) V19(IO_L02P_1/LDC1)

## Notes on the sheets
sheet 28
- FPGA, SYSREF Buffering, LEDs
- Bank0(1.8V)
- Bank1(1.8V)
- 1.8V Bidirectional I/O
- Tristated
  Bootpin GPIOs
- Note: Place these TPs nearer
- SYSREF_P/N output from FPGA is LVDS pair
  FPGA_CLK_P/N input to FPGA is LVDS pair
- SYSREF_DIVCLK input to FPGA is LVDS pair
- Note: Place these TPs nearer
- Place near FPGA pins
- LVDS
- LVPECL
- Note:LED Color is GREEN
- Note:LED Color is RED
